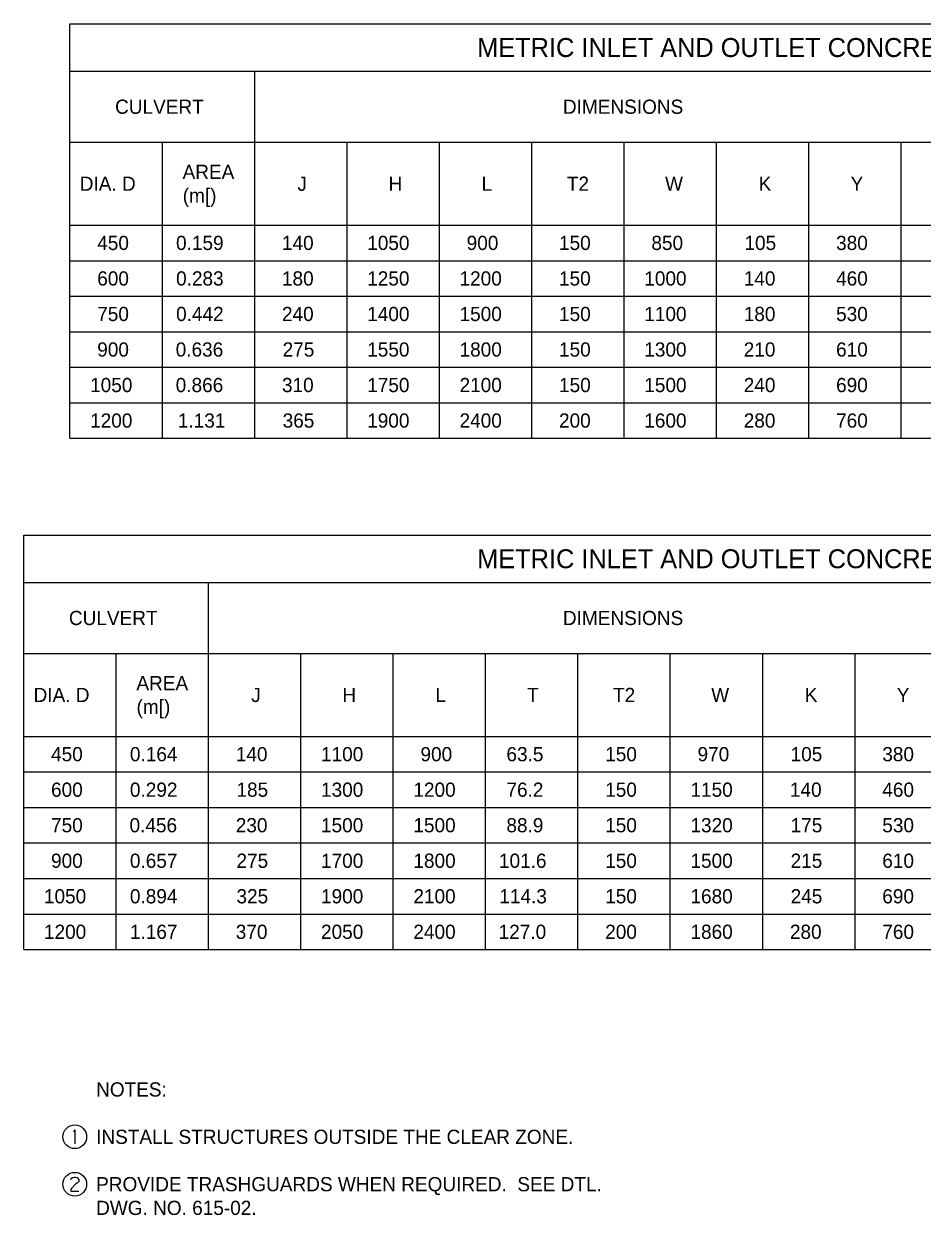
# Model space of a CAD drawing. Extents: x 49991.4 to 50043, y 49987.6 to 50011.4.
# Drawn here: x 50034.98 to 50038.78, y 49988.22 to 49993.25 of the extents above; entities that cross this region are included whole.
import ezdxf

# ---------------------------------------------------------------- set-up
doc = ezdxf.new("R2010")
doc.units = 0
doc.layers.add('Level 2', color=7, linetype='Continuous')

msp = doc.modelspace()

# ---------------------------------------------------------------- linework, layer by layer
at = {"layer": 'Level 2'}
for p, q in [((50035.1783, 49993.2523), (50042.5883, 49993.2523)), ((50035.1783, 49993.0523), (50042.5883, 49993.0523)), ((50035.1783, 49992.7523), (50042.5883, 49992.7523)), ((50035.1783, 49992.4023), (50042.5883, 49992.4023)), ((50035.1783, 49992.2523), (50042.5883, 49992.2523)), ((50035.1783, 49992.1023), (50042.5883, 49992.1023)), ((50035.1783, 49991.9523), (50042.5883, 49991.9523)), ((50035.1783, 49991.8023), (50042.5883, 49991.8023)), ((50035.1783, 49991.6523), (50042.5883, 49991.6523)), ((50035.1783, 49991.5023), (50042.5883, 49991.5023)), ((50035.1986, 49988.583), (50035.1927, 49988.5726)), ((50035.1986, 49988.583), (50035.1986, 49988.523))]:
    msp.add_line(p, q, dxfattribs=at)
for points in [[(50035.1783, 49991.5023), (50035.1783, 49993.2523)], [(50035.9583, 49991.5023), (50035.9583, 49993.0523)], [(50035.5683, 49991.5023), (50035.5683, 49992.7523)], [(50036.3483, 49991.5023), (50036.3483, 49992.7523)], [(50036.7383, 49991.5023), (50036.7383, 49992.7523)], [(50037.1283, 49991.5023), (50037.1283, 49992.7523)], [(50037.5183, 49991.5023), (50037.5183, 49992.7523)], [(50037.9083, 49991.5023), (50037.9083, 49992.7523)], [(50038.2983, 49991.5023), (50038.2983, 49992.7523)], [(50038.6883, 49991.5023), (50038.6883, 49992.7523)], [(50034.9833, 49989.3437), (50034.9833, 49991.0937)], [(50034.9833, 49991.0937), (50042.7833, 49991.0937)], [(50034.9833, 49990.8937), (50042.7833, 49990.8937)], [(50035.7633, 49989.3437), (50035.7633, 49990.8937)], [(50034.9833, 49990.5937), (50042.7833, 49990.5937)], [(50035.3733, 49989.3437), (50035.3733, 49990.5937)], [(50036.1533, 49989.3437), (50036.1533, 49990.5937)], [(50036.5433, 49989.3437), (50036.5433, 49990.5937)], [(50036.9333, 49989.3437), (50036.9333, 49990.5937)], [(50037.3233, 49989.3437), (50037.3233, 49990.5937)], [(50037.7133, 49989.3437), (50037.7133, 49990.5937)], [(50038.1033, 49989.3437), (50038.1033, 49990.5937)], [(50038.4933, 49989.3437), (50038.4933, 49990.5937)], [(50034.9833, 49990.2437), (50042.7833, 49990.2437)], [(50034.9833, 49990.0937), (50042.7833, 49990.0937)], [(50034.9833, 49989.9437), (50042.7833, 49989.9437)], [(50034.9833, 49989.7937), (50042.7833, 49989.7937)], [(50034.9833, 49989.6437), (50042.7833, 49989.6437)], [(50034.9833, 49989.4937), (50042.7833, 49989.4937)], [(50034.9833, 49989.3437), (50042.7833, 49989.3437)], [(50035.1817, 49988.3708), (50035.1836, 49988.3765), (50035.1888, 49988.3812), (50035.1959, 49988.3831), (50035.2011, 49988.3831), (50035.2081, 49988.3812), (50035.2133, 49988.376), (50035.2157, 49988.3708), (50035.2157, 49988.3656), (50035.2138, 49988.3613), (50035.202, 49988.3524), (50035.1836, 49988.3335), (50035.1817, 49988.3287), (50035.1817, 49988.3231), (50035.2157, 49988.3231)]]:
    msp.add_lwpolyline(points, dxfattribs=at)
for centre in [(50035.1986, 49988.553), (50035.1986, 49988.353)]:
    msp.add_circle(centre, 0.05, dxfattribs=at)

# ---------------------------------------------------------------- texts
for s, height, p in [('METRIC INLET AND OUTLET CONCRETE TRANSITIONS FOR CSP', 0.08, (50036.898, 49993.1123)), ('CULVERT', 0.06, (50035.3687, 49992.8723)), ('DIMENSIONS', 0.06, (50037.2597, 49992.8723)), ('AREA', 0.06, (50035.6537, 49992.5973)), ('DIA. D', 0.06, (50035.2195, 49992.5473)), ('J', 0.06, (50036.1385, 49992.5473)), ('H', 0.06, (50036.5237, 49992.5473)), ('L', 0.06, (50036.9163, 49992.5473)), ('T2', 0.06, (50037.2763, 49992.5473)), ('W', 0.06, (50037.6911, 49992.5473)), ('K', 0.06, (50038.0863, 49992.5473)), ('Y', 0.06, (50038.4745, 49992.5473)), ('(m[)', 0.06, (50035.6543, 49992.4973)), ('450', 0.06, (50035.2933, 49992.2973)), ('0.159', 0.06, (50035.6261, 49992.2973)), ('140', 0.06, (50036.0733, 49992.2973)), ('1050', 0.06, (50036.4333, 49992.2973)), ('900', 0.06, (50036.8533, 49992.2973)), ('150', 0.06, (50037.2433, 49992.2973)), ('850', 0.06, (50037.6333, 49992.2973)), ('105', 0.06, (50038.0263, 49992.2973)), ('380', 0.06, (50038.4133, 49992.2973)), ('600', 0.06, (50035.2933, 49992.1473)), ('0.283', 0.06, (50035.6263, 49992.1473)), ('180', 0.06, (50036.0733, 49992.1473)), ('1250', 0.06, (50036.4333, 49992.1473)), ('1200', 0.06, (50036.8233, 49992.1473)), ('150', 0.06, (50037.2433, 49992.1473)), ('1000', 0.06, (50037.6033, 49992.1473)), ('140', 0.06, (50038.0233, 49992.1473)), ('460', 0.06, (50038.4133, 49992.1473)), ('750', 0.06, (50035.2933, 49991.9973)), ('0.442', 0.06, (50035.6263, 49991.9973)), ('240', 0.06, (50036.0733, 49991.9973)), ('1400', 0.06, (50036.4333, 49991.9973)), ('1500', 0.06, (50036.8233, 49991.9973)), ('150', 0.06, (50037.2433, 49991.9973)), ('1100', 0.06, (50037.6033, 49991.9973)), ('180', 0.06, (50038.0233, 49991.9973)), ('530', 0.06, (50038.4133, 49991.9973)), ('900', 0.06, (50035.2933, 49991.8473)), ('0.636', 0.06, (50035.6247, 49991.8473)), ('275', 0.06, (50036.0763, 49991.8473)), ('1550', 0.06, (50036.4333, 49991.8473)), ('1800', 0.06, (50036.8233, 49991.8473)), ('150', 0.06, (50037.2433, 49991.8473)), ('1300', 0.06, (50037.6033, 49991.8473)), ('210', 0.06, (50038.0233, 49991.8473)), ('610', 0.06, (50038.4133, 49991.8473)), ('1050', 0.06, (50035.2633, 49991.6973)), ('0.866', 0.06, (50035.6247, 49991.6973)), ('310', 0.06, (50036.0733, 49991.6973)), ('1750', 0.06, (50036.4333, 49991.6973)), ('2100', 0.06, (50036.8233, 49991.6973)), ('150', 0.06, (50037.2433, 49991.6973)), ('1500', 0.06, (50037.6033, 49991.6973)), ('240', 0.06, (50038.0233, 49991.6973)), ('690', 0.06, (50038.4133, 49991.6973)), ('1200', 0.06, (50035.2633, 49991.5473)), ('1.131', 0.06, (50035.6337, 49991.5473)), ('365', 0.06, (50036.0763, 49991.5473)), ('1900', 0.06, (50036.4333, 49991.5473)), ('2400', 0.06, (50036.8233, 49991.5473)), ('200', 0.06, (50037.2433, 49991.5473)), ('1600', 0.06, (50037.6033, 49991.5473)), ('280', 0.06, (50038.0233, 49991.5473)), ('760', 0.06, (50038.4133, 49991.5473)), ('METRIC INLET AND OUTLET CONCRETE TRANSITIONS FOR RCP', 0.08, (50036.898, 49990.9537)), ('CULVERT', 0.06, (50035.1737, 49990.7137)), ('DIMENSIONS', 0.06, (50037.2597, 49990.7137)), ('AREA', 0.06, (50035.4587, 49990.4387)), ('DIA. D', 0.06, (50035.0245, 49990.3887)), ('(m[)', 0.06, (50035.4593, 49990.3387)), ('J', 0.06, (50035.9435, 49990.3887)), ('H', 0.06, (50036.3287, 49990.3887)), ('L', 0.06, (50036.7213, 49990.3887)), ('T', 0.06, (50037.1087, 49990.3887)), ('T2', 0.06, (50037.4713, 49990.3887)), ('W', 0.06, (50037.8861, 49990.3887)), ('K', 0.06, (50038.2813, 49990.3887)), ('Y', 0.06, (50038.6695, 49990.3887)), ('450', 0.06, (50035.0983, 49990.1387)), ('0.164', 0.06, (50035.4313, 49990.1387)), ('140', 0.06, (50035.8783, 49990.1387)), ('1100', 0.06, (50036.2383, 49990.1387)), ('900', 0.06, (50036.6583, 49990.1387)), ('63.5', 0.06, (50037.0213, 49990.1387)), ('150', 0.06, (50037.4383, 49990.1387)), ('970', 0.06, (50037.8283, 49990.1387)), ('105', 0.06, (50038.2213, 49990.1387)), ('380', 0.06, (50038.6083, 49990.1387)), ('600', 0.06, (50035.0983, 49989.9887)), ('0.292', 0.06, (50035.4313, 49989.9887)), ('185', 0.06, (50035.8813, 49989.9887)), ('1300', 0.06, (50036.2383, 49989.9887)), ('1200', 0.06, (50036.6283, 49989.9887)), ('76.2', 0.06, (50037.0213, 49989.9887)), ('150', 0.06, (50037.4383, 49989.9887)), ('1150', 0.06, (50037.7983, 49989.9887)), ('140', 0.06, (50038.2183, 49989.9887)), ('460', 0.06, (50038.6083, 49989.9887)), ('750', 0.06, (50035.0983, 49989.8387)), ('0.456', 0.06, (50035.4297, 49989.8387)), ('230', 0.06, (50035.8783, 49989.8387)), ('1500', 0.06, (50036.2383, 49989.8387)), ('1500', 0.06, (50036.6283, 49989.8387)), ('88.9', 0.06, (50037.0211, 49989.8387)), ('150', 0.06, (50037.4383, 49989.8387)), ('1320', 0.06, (50037.7983, 49989.8387)), ('530', 0.06, (50038.6083, 49989.8387)), ('175', 0.06, (50038.2213, 49989.8387)), ('900', 0.06, (50035.0983, 49989.6887)), ('0.657', 0.06, (50035.4313, 49989.6887)), ('275', 0.06, (50035.8813, 49989.6887)), ('1700', 0.06, (50036.2383, 49989.6887)), ('1800', 0.06, (50036.6283, 49989.6887)), ('101.6', 0.06, (50036.9897, 49989.6887)), ('150', 0.06, (50037.4383, 49989.6887)), ('1500', 0.06, (50037.7983, 49989.6887)), ('215', 0.06, (50038.2213, 49989.6887)), ('610', 0.06, (50038.6083, 49989.6887)), ('1050', 0.06, (50035.0683, 49989.5387)), ('0.894', 0.06, (50035.4313, 49989.5387)), ('325', 0.06, (50035.8813, 49989.5387)), ('1900', 0.06, (50036.2383, 49989.5387)), ('2100', 0.06, (50036.6283, 49989.5387)), ('114.3', 0.06, (50036.9913, 49989.5387)), ('150', 0.06, (50037.4383, 49989.5387)), ('1680', 0.06, (50037.7983, 49989.5387)), ('245', 0.06, (50038.2213, 49989.5387)), ('690', 0.06, (50038.6083, 49989.5387)), ('1200', 0.06, (50035.0683, 49989.3887)), ('1.167', 0.06, (50035.4313, 49989.3887)), ('370', 0.06, (50035.8783, 49989.3887)), ('2050', 0.06, (50036.2383, 49989.3887)), ('2400', 0.06, (50036.6283, 49989.3887)), ('127.0', 0.06, (50036.9883, 49989.3887)), ('200', 0.06, (50037.4383, 49989.3887)), ('1860', 0.06, (50037.7983, 49989.3887)), ('280', 0.06, (50038.2183, 49989.3887)), ('760', 0.06, (50038.6083, 49989.3887)), ('NOTES:', 0.06, (50035.2886, 49988.723)), ('INSTALL STRUCTURES OUTSIDE THE CLEAR ZONE.', 0.06, (50035.2886, 49988.523)), ('PROVIDE TRASHGUARDS WHEN REQUIRED.  SEE DTL.', 0.06, (50035.2886, 49988.323)), ('DWG. NO. 615-02.', 0.06, (50035.2886, 49988.223))]:
    msp.add_text(s, height=height, dxfattribs=at).set_placement(p)

doc.saveas('drawing.dxf')
